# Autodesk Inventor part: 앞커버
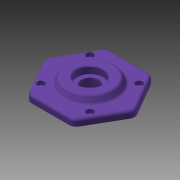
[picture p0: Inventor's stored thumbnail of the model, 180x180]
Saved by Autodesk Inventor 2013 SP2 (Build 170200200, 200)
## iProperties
Created: 2013-02
Part Number: 앞커버
Document SubType Name: Modeling
Density: 1 g/cm^3
Material: 일반
Author: 한국산업디자인학원[gmhk.co.kr]
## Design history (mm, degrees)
sketch "스케치1" dims "d37" = 105
  geometry: L1 (28.559, 41.466)-(50.191, 4); L2 (50.191, -4)-(28.559, -41.466); L3 (21.631, -45.466)-(-21.631, -45.466); L4 (-28.559, -41.466)-(-50.191, -4); L5 (-50.191, 4)-(-28.559, 41.466); L6 (-21.631, 45.466)-(21.631, 45.466); C1 r 30 at (0, 0); A1 r 8 centre (-43.262, 0) between (-50.191, 4) and (-50.191, -4); A2 r 8 centre (-21.631, 37.466) between (-21.631, 45.466) and (-28.559, 41.466); A3 r 8 centre (21.631, 37.466) between (28.559, 41.466) and (21.631, 45.466); A4 r 8 centre (43.262, 0) between (50.191, -4) and (50.191, 4); A5 r 8 centre (21.631, -37.466) between (21.631, -45.466) and (28.559, -41.466); A6 r 8 centre (-21.631, -37.466) between (-28.559, -41.466) and (-21.631, -45.466); 9 further points
  constraints: 12 end point, 12 point on circle, 12 point on line, 12 tangent, 7 centre point, 5 equal radius, 3 coincident, 1 horizontal, 16 other
  dimensions: "d40" = 8 radius of A1; "d41" = 60 diameter of C1
extrude "돌출1" new body sketch "스케치1" distance "d0" = 8; taper "d1" = 0 deg
sketch "스케치2"
  geometry: C1 r 30 at (0, 0); 1 further point
  constraints: 1 centre point, 1 coincident
  dimensions: "d2" = 60 diameter of C1
extrude "돌출2" join sketch "스케치2" distance "d3" = 7; taper "d4" = -30 deg
hole "구멍1" diameter "d7" = 20; stored, may be unused: countersink angle "d11" = 90 deg, drill point angle "d13" = 118 deg; dims "d8" = 6, "d9" = 30, "d10" = 8.3, "d12" = 20, "d52" = 10, "d53" = 10
sketch "스케치3"
  geometry: L1 (-28.284, 28.284)-(0, 0); L2 (0, 0)-(0, 40); L3 (0, 0)-(28.284, 28.284); L4 (0, 0)-(28.284, -28.284); L5 (0, 0)-(-28.284, -28.284); C1 r 1.621 at (28.284, 28.284); C2 r 1.621 at (-28.284, 28.284); C3 r 1.621 at (-28.284, -28.284); C4 r 1.621 at (28.284, -28.284); C5 r 10 at (0, 0) reference; A1 r 40 centre (0, 0) between (28.284, 28.284) and (-28.284, 28.284)
  constraints: 10 end point, 5 centre point, 3 perpendicular, 3 point on circle, 1 coincident, 1 vertical
  dimensions: "d48" = 80 diameter of A1; "d50" = 45 deg angle of L2 L1
hole "구멍2" sketch "스케치3" at (28.284, 28.284), (28.284, -28.284), (-28.284, -28.284), (-28.284, 28.284) diameter "d14" = 4.5; stored, may be unused: countersink angle "d18" = 90 deg, drill point angle "d20" = 118 deg; dims "d15" = 6, "d16" = 8, "d17" = 4.4, "d19" = 20
extrude "돌출3" join sketch "스케치1" distance "d21" = 12; taper "d22" = 0 deg
hole "구멍3" diameter "d25" = 30; stored, may be unused: countersink angle "d29" = 90 deg, drill point angle "d31" = 0 deg; dims "d26" = 6, "d27" = 40, "d28" = 12, "d30" = 15, "d42" = 10, "d43" = 10
fillet "모깎기1" dims "d32" = 3, "d33" = 0.3
chamfer "모따기1" distance "d34" = 1; stored, may be unused: second distance "d35" = 2, angle "d36" = 45 deg
chamfer "모따기2" distance "d44" = 1; stored, may be unused: second distance "d45" = 2, angle "d46" = 45 deg
fillet "모깎기2" dims "d47" = 3
fillet "모깎기3" dims "d54" = 0.6
node "솔리드1"
